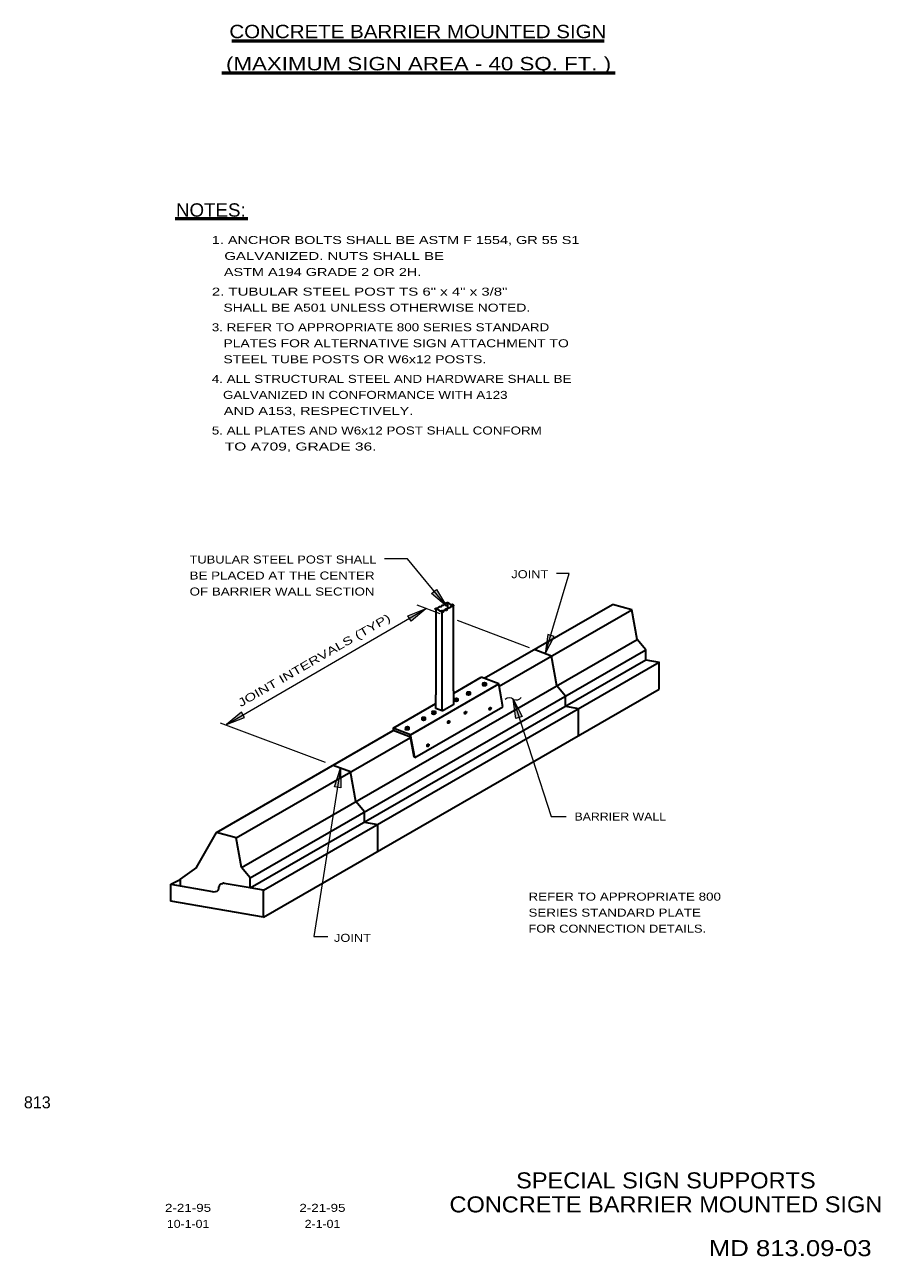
# Model space of a CAD drawing. Extents: x 5940.27 to 5946.69, y 1537.87 to 1547.1.
import ezdxf
from ezdxf.enums import TextEntityAlignment as Align

# ---------------------------------------------------------------- set-up
doc = ezdxf.new("R2010")
doc.units = 0
doc.header["$LTSCALE"] = 0.024
doc.header["$PDMODE"] = 32
doc.header["$PDSIZE"] = 0.012
for name, color, linetype, lineweight in [('1', 7, 'Continuous', 35), ('10', 7, 'Continuous', 13), ('12', 7, 'Continuous', 53), ('13', 7, 'Continuous', 53)]:
    doc.layers.add(name, color=color, linetype=linetype, lineweight=lineweight)

msp = doc.modelspace()

# ---------------------------------------------------------------- hatches: boundary and pattern name
at = {"layer": '10'}
for points in [[(5943.325, 1542.835), (5943.361, 1542.866), (5943.436, 1542.741)], [(5943.173, 1542.628), (5943.147, 1542.669), (5943.284, 1542.722)], [(5944.244, 1542.514), (5944.198, 1542.528), (5944.177, 1542.384)], [(5944.005, 1541.912), (5943.957, 1541.897), (5943.936, 1542.042)], [(5941.923, 1541.905), (5941.9, 1541.946), (5941.786, 1541.853)], [(5942.645, 1541.379), (5942.596, 1541.387), (5942.643, 1541.526)]]:
    msp.add_hatch(color=256, dxfattribs=at).paths.add_polyline_path(points)

# ---------------------------------------------------------------- linework, layer by layer
at = {"layer": '1'}
for p, q in [((5943.359, 1542.075), (5943.359, 1542.719)), ((5943.405, 1542.056), (5943.405, 1542.698)), ((5943.444, 1542.767), (5943.444, 1542.724)), ((5943.489, 1542.655), (5943.489, 1542.744)), ((5943.72, 1542.2), (5944.682, 1542.754)), ((5943.831, 1542.14), (5944.827, 1542.714)), ((5944.827, 1542.714), (5944.682, 1542.754)), ((5944.867, 1542.491), (5944.827, 1542.714)), ((5943.489, 1542.105), (5943.489, 1542.655)), ((5941.9, 1540.781), (5944.867, 1542.491)), ((5941.964, 1540.703), (5944.933, 1542.414)), ((5944.224, 1542.366), (5944.095, 1542.415)), ((5944.933, 1542.414), (5944.867, 1542.491)), ((5944.933, 1542.338), (5944.933, 1542.414)), ((5941.964, 1540.628), (5944.933, 1542.338)), ((5942.064, 1540.611), (5945.031, 1542.32)), ((5944.264, 1542.143), (5944.224, 1542.366)), ((5944.933, 1542.338), (5945.031, 1542.32)), ((5945.031, 1542.119), (5945.031, 1542.32)), ((5943.168, 1541.777), (5943.829, 1542.158)), ((5943.491, 1542.088), (5943.698, 1542.208)), ((5943.829, 1542.158), (5943.698, 1542.208)), ((5943.709, 1542.164), (5943.709, 1542.147)), ((5943.709, 1542.164), (5943.709, 1542.147)), ((5943.709, 1542.164), (5943.709, 1542.147)), ((5943.709, 1542.164), (5943.709, 1542.147)), ((5943.734, 1542.163), (5943.734, 1542.146)), ((5943.734, 1542.163), (5943.734, 1542.146)), ((5943.734, 1542.163), (5943.734, 1542.146)), ((5943.734, 1542.163), (5943.734, 1542.146)), ((5943.86, 1541.986), (5943.829, 1542.158)), ((5944.33, 1542.066), (5944.264, 1542.143)), ((5942.064, 1540.408), (5945.031, 1542.119)), ((5943.357, 1541.973), (5943.357, 1542.075)), ((5943.404, 1541.956), (5943.404, 1542.055)), ((5943.498, 1542.048), (5943.498, 1542.031)), ((5943.498, 1542.048), (5943.498, 1542.031)), ((5943.523, 1542.047), (5943.523, 1542.03)), ((5943.523, 1542.047), (5943.523, 1542.03)), ((5943.59, 1542.096), (5943.59, 1542.079)), ((5943.59, 1542.096), (5943.59, 1542.079)), ((5943.59, 1542.096), (5943.59, 1542.079)), ((5943.59, 1542.096), (5943.59, 1542.079)), ((5943.615, 1542.095), (5943.615, 1542.078)), ((5943.615, 1542.095), (5943.615, 1542.078)), ((5943.615, 1542.095), (5943.615, 1542.078)), ((5943.615, 1542.095), (5943.615, 1542.078)), ((5944.33, 1541.99), (5944.33, 1542.066)), ((5943.037, 1541.826), (5943.357, 1542.01)), ((5943.199, 1541.605), (5943.86, 1541.986)), ((5943.329, 1541.951), (5943.329, 1541.934)), ((5943.354, 1541.95), (5943.354, 1541.933)), ((5943.404, 1541.956), (5943.357, 1541.973)), ((5944.33, 1541.99), (5944.428, 1541.972)), ((5944.428, 1541.771), (5944.428, 1541.972)), ((5943.253, 1541.906), (5943.253, 1541.889)), ((5943.278, 1541.905), (5943.278, 1541.888)), ((5941.713, 1541.043), (5943.038, 1541.807)), ((5943.168, 1541.777), (5943.037, 1541.826)), ((5943.037, 1541.826), (5943.037, 1541.806)), ((5943.168, 1541.758), (5943.038, 1541.807)), ((5943.13, 1541.834), (5943.13, 1541.817)), ((5943.155, 1541.833), (5943.155, 1541.816)), ((5943.168, 1541.777), (5943.168, 1541.758)), ((5943.199, 1541.605), (5943.168, 1541.777)), ((5941.86, 1541.004), (5943.166, 1541.757)), ((5943.195, 1541.608), (5943.168, 1541.758)), ((5943.194, 1541.608), (5943.198, 1541.606)), ((5942.717, 1541.498), (5942.588, 1541.547)), ((5942.757, 1541.275), (5942.717, 1541.498)), ((5942.823, 1541.198), (5942.757, 1541.275)), ((5942.823, 1541.122), (5942.823, 1541.198)), ((5942.823, 1541.122), (5942.921, 1541.104)), ((5941.562, 1540.781), (5941.713, 1541.043)), ((5941.86, 1541.004), (5941.713, 1541.043)), ((5942.921, 1540.903), (5942.921, 1541.104)), ((5941.369, 1540.656), (5941.439, 1540.692)), ((5941.369, 1540.529), (5941.369, 1540.656)), ((5941.369, 1540.656), (5941.682, 1540.601)), ((5941.964, 1540.628), (5941.769, 1540.662)), ((5942.064, 1540.408), (5942.064, 1540.611)), ((5942.064, 1540.408), (5941.369, 1540.529))]:
    msp.add_line(p, q, dxfattribs=at)
for points in [[(5943.358, 1542.719), (5943.361, 1542.722), (5943.362, 1542.722), (5943.365, 1542.724), (5943.367, 1542.724), (5943.368, 1542.724), (5943.368, 1542.725), (5943.371, 1542.725), (5943.372, 1542.727), (5943.374, 1542.727), (5943.375, 1542.728), (5943.376, 1542.731), (5943.378, 1542.734), (5943.381, 1542.735), (5943.382, 1542.735), (5943.384, 1542.737), (5943.385, 1542.737), (5943.386, 1542.737), (5943.389, 1542.738), (5943.392, 1542.738), (5943.396, 1542.738), (5943.399, 1542.739), (5943.401, 1542.741), (5943.402, 1542.742), (5943.404, 1542.744), (5943.404, 1542.745), (5943.405, 1542.747), (5943.406, 1542.747), (5943.408, 1542.749), (5943.411, 1542.749), (5943.412, 1542.749), (5943.415, 1542.749), (5943.416, 1542.751), (5943.418, 1542.752), (5943.421, 1542.754), (5943.425, 1542.757), (5943.428, 1542.759), (5943.431, 1542.761), (5943.432, 1542.764), (5943.434, 1542.764)], [(5943.402, 1542.701), (5943.399, 1542.701), (5943.398, 1542.704), (5943.395, 1542.704), (5943.392, 1542.704), (5943.389, 1542.704), (5943.386, 1542.704), (5943.385, 1542.705), (5943.384, 1542.707), (5943.384, 1542.708), (5943.382, 1542.708), (5943.381, 1542.711), (5943.378, 1542.711), (5943.376, 1542.712), (5943.374, 1542.714), (5943.369, 1542.715), (5943.367, 1542.715), (5943.365, 1542.715), (5943.362, 1542.717), (5943.361, 1542.717), (5943.359, 1542.719)], [(5943.411, 1542.701), (5943.406, 1542.7), (5943.405, 1542.7), (5943.405, 1542.698), (5943.404, 1542.7), (5943.402, 1542.701)], [(5943.436, 1542.715), (5943.435, 1542.714), (5943.434, 1542.712), (5943.432, 1542.711), (5943.429, 1542.711), (5943.426, 1542.709), (5943.425, 1542.709), (5943.422, 1542.709), (5943.421, 1542.709), (5943.419, 1542.708), (5943.418, 1542.708), (5943.416, 1542.707), (5943.415, 1542.705), (5943.414, 1542.704), (5943.412, 1542.704), (5943.411, 1542.701)], [(5943.434, 1542.764), (5943.435, 1542.764), (5943.436, 1542.764), (5943.438, 1542.764), (5943.441, 1542.764), (5943.442, 1542.765), (5943.442, 1542.767), (5943.444, 1542.767), (5943.445, 1542.767), (5943.446, 1542.767), (5943.448, 1542.765), (5943.449, 1542.764), (5943.451, 1542.764), (5943.452, 1542.764), (5943.456, 1542.761), (5943.458, 1542.761), (5943.459, 1542.761), (5943.462, 1542.759), (5943.462, 1542.758), (5943.462, 1542.755), (5943.464, 1542.755), (5943.464, 1542.754), (5943.466, 1542.754), (5943.468, 1542.754), (5943.473, 1542.754), (5943.475, 1542.752), (5943.476, 1542.752), (5943.478, 1542.752), (5943.479, 1542.751), (5943.481, 1542.749)], [(5943.481, 1542.749), (5943.482, 1542.749), (5943.485, 1542.749), (5943.486, 1542.747), (5943.488, 1542.747), (5943.489, 1542.747), (5943.489, 1542.745), (5943.489, 1542.744), (5943.488, 1542.742), (5943.486, 1542.741), (5943.482, 1542.739), (5943.481, 1542.739), (5943.478, 1542.738), (5943.476, 1542.738), (5943.473, 1542.738), (5943.472, 1542.738), (5943.471, 1542.737), (5943.471, 1542.735), (5943.468, 1542.735), (5943.466, 1542.734), (5943.466, 1542.731), (5943.464, 1542.729), (5943.462, 1542.727), (5943.458, 1542.727), (5943.455, 1542.725), (5943.451, 1542.725), (5943.446, 1542.725), (5943.445, 1542.725), (5943.444, 1542.724), (5943.442, 1542.722), (5943.441, 1542.719), (5943.438, 1542.719), (5943.436, 1542.715)], [(5943.404, 1541.956), (5943.491, 1542.006), (5943.491, 1542.105)], [(5942.064, 1540.611), (5941.964, 1540.628), (5941.964, 1540.703), (5941.9, 1540.781), (5941.86, 1541.004)], [(5941.562, 1540.781), (5941.439, 1540.693), (5941.439, 1540.644)], [(5941.68, 1540.601), (5941.682, 1540.601), (5941.693, 1540.599), (5941.704, 1540.602), (5941.716, 1540.604), (5941.722, 1540.609), (5941.727, 1540.615), (5941.729, 1540.626), (5941.729, 1540.636), (5941.734, 1540.645), (5941.74, 1540.654), (5941.747, 1540.658), (5941.754, 1540.661), (5941.759, 1540.662)]]:
    msp.add_lwpolyline(points, dxfattribs=at)
msp.add_arc((5941.76591, 1540.64391), 0.01907, 79.2457, 110.19528, dxfattribs=at)
for centre, major_axis in [((5943.72127, 1542.1497), (0.01323, 0)), ((5943.72127, 1542.1497), (0.01323, 0)), ((5943.72127, 1542.1497), (0.01323, 0)), ((5943.72127, 1542.1497), (0.01323, 0)), ((5943.72227, 1542.1597), (0.01323, 0)), ((5943.72227, 1542.1597), (0.01323, 0)), ((5943.72227, 1542.1597), (0.01323, 0)), ((5943.72227, 1542.1597), (0.01323, 0)), ((5943.51027, 1542.0337), (0.01323, 0)), ((5943.51027, 1542.0337), (0.01323, 0)), ((5943.51127, 1542.0437), (0.01323, 0)), ((5943.51127, 1542.0437), (0.01323, 0)), ((5943.60227, 1542.0817), (0.01323, 0)), ((5943.60227, 1542.0817), (0.01323, 0)), ((5943.60227, 1542.0817), (0.01323, 0)), ((5943.60227, 1542.0817), (0.01323, 0)), ((5943.60327, 1542.0917), (0.01323, 0)), ((5943.60327, 1542.0917), (0.01323, 0)), ((5943.60327, 1542.0917), (0.01323, 0)), ((5943.60327, 1542.0917), (0.01323, 0)), ((5943.34127, 1541.9367), (0.01323, 0)), ((5943.34227, 1541.9467), (0.01323, 0)), ((5943.57927, 1541.9427), (0.00511, 0.00884)), ((5943.76427, 1541.9727), (0.00511, 0.00884)), ((5943.26527, 1541.8917), (0.01323, 0)), ((5943.26627, 1541.9017), (0.01323, 0)), ((5943.45327, 1541.8717), (0.00511, 0.00884)), ((5943.14227, 1541.8197), (0.01323, 0)), ((5943.14327, 1541.8297), (0.01323, 0)), ((5943.29827, 1541.6977), (0.00511, 0.00884))]:
    msp.add_ellipse(centre, major_axis=major_axis, ratio=0.57735, dxfattribs=at)
for p in [(5943.359, 1542.719), (5943.402, 1542.701), (5943.411, 1542.701), (5943.436, 1542.715), (5943.481, 1542.749)]:
    msp.add_point(p, dxfattribs=at)
at = {"layer": '10'}
for p, q in [((5941.786, 1541.852), (5943.285, 1542.724)), ((5943.389, 1542.684), (5943.218, 1542.748)), ((5944.059, 1542.429), (5943.519, 1542.634)), ((5942.53, 1541.569), (5941.743, 1541.863))]:
    msp.add_line(p, q, dxfattribs=at)
for points in [[(5943.436, 1542.741), (5943.144, 1543.096), (5942.973, 1543.096)], [(5944.177, 1542.384), (5944.357, 1542.985), (5944.261, 1542.985)], [(5943.936, 1542.042), (5944.223, 1541.164), (5944.334, 1541.163)], [(5942.643, 1541.526), (5942.443, 1540.265), (5942.548, 1540.265)]]:
    msp.add_lwpolyline(points, dxfattribs=at)
for points in [[(5943.325, 1542.835), (5943.361, 1542.866), (5943.436, 1542.741)], [(5943.173, 1542.628), (5943.147, 1542.669), (5943.284, 1542.722)], [(5944.244, 1542.514), (5944.198, 1542.528), (5944.177, 1542.384)], [(5944.005, 1541.912), (5943.957, 1541.897), (5943.936, 1542.042)], [(5941.923, 1541.905), (5941.9, 1541.946), (5941.786, 1541.853)], [(5942.645, 1541.379), (5942.596, 1541.387), (5942.643, 1541.526)]]:
    msp.add_lwpolyline(points, close=True, dxfattribs=at)
for centre, radius, start, end in [((5943.90928, 1542.00444), 0.04844, 50.11598, 129.88402), ((5943.96061, 1542.08336), 0.04641, 244.09904, 322.98165)]:
    msp.add_arc(centre, radius, start, end, dxfattribs=at)
at = {"layer": '12'}
for p, q in [((5941.826, 1546.978), (5944.62, 1546.978)), ((5941.752, 1546.737), (5944.703, 1546.737))]:
    msp.add_line(p, q, dxfattribs=at)
at = {"layer": '13'}
msp.add_line((5941.402, 1545.647), (5941.947, 1545.647), dxfattribs=at)

# ---------------------------------------------------------------- texts
at = {"layer": '12'}
for s, width, p in [('CONCRETE BARRIER MOUNTED SIGN', 1.15, (5943.2225, 1546.998)), ('(MAXIMUM SIGN AREA - 40 SQ. FT. )', 1.25, (5943.2275, 1546.757))]:
    msp.add_text(s, height=0.1, dxfattribs=dict(at, width=width)).set_placement(p, align=Align.CENTER)
for s, width, p in [('TUBULAR STEEL POST SHALL', 1.2, (5941.51, 1543.06)), ('BE PLACED AT THE CENTER', 1.25, (5941.51, 1542.94)), ('JOINT', 1.2, (5943.923, 1542.95)), ('OF BARRIER WALL SECTION', 1.25, (5941.51, 1542.82)), ('BARRIER WALL', 1.15, (5944.397, 1541.133)), ('REFER TO APPROPRIATE 800', 1.25, (5944.052, 1540.533)), ('SERIES STANDARD PLATE ', 1.25, (5944.052, 1540.413)), ('JOINT', 1.2, (5942.593, 1540.224)), ('FOR CONNECTION DETAILS.', 1.2, (5944.052, 1540.293))]:
    msp.add_text(s, height=0.06, dxfattribs=dict(at, width=width)).set_placement(p)
at = {"layer": '12', "width": 1.4}
msp.add_text(' JOINT INTERVALS (TYP)', height=0.06, rotation=30, dxfattribs=at).set_placement((5941.867, 1541.967))
at = {"layer": '13'}
for s, height, width, p in [('NOTES:', 0.1, 1.05, (5941.6695, 1545.66)), ('SPECIAL SIGN SUPPORTS', 0.12, 1.1, (5945.0825, 1538.376)), ('2-21-95', 0.06, 1.25, (5941.4985, 1538.2)), ('2-21-95', 0.06, 1.25, (5942.5065, 1538.2)), ('CONCRETE BARRIER MOUNTED SIGN', 0.12, 1.1, (5945.0825, 1538.196)), ('10-1-01', 0.06, 1.15, (5941.499, 1538.08)), ('2-1-01', 0.06, 1.15, (5942.507, 1538.08)), ('MD 813.09-03', 0.12, 1.2, (5946.015, 1537.868))]:
    msp.add_text(s, height=height, dxfattribs=dict(at, width=width)).set_placement(p, align=Align.CENTER)
for s, width, p in [('1. ANCHOR BOLTS SHALL BE ASTM F 1554, GR 55 S1', 1.35, (5941.677, 1545.455)), ('   GALVANIZED. NUTS SHALL BE ', 1.4, (5941.677, 1545.335)), ('   ASTM A194 GRADE 2 OR 2H.', 1.35, (5941.677, 1545.215)), ('2. TUBULAR STEEL POST TS 6" x 4" x 3/8"', 1.4, (5941.677, 1545.068)), ('   SHALL BE A501 UNLESS OTHERWISE NOTED.', 1.3, (5941.677, 1544.948)), ('3. REFER TO APPROPRIATE 800 SERIES STANDARD', 1.25, (5941.677, 1544.801)), ('   PLATES FOR ALTERNATIVE SIGN ATTACHMENT TO', 1.3, (5941.677, 1544.681)), ('   STEEL TUBE POSTS OR W6x12 POSTS.', 1.3, (5941.677, 1544.561)), ('4. ALL STRUCTURAL STEEL AND HARDWARE SHALL BE', 1.25, (5941.677, 1544.414)), ('   GALVANIZED IN CONFORMANCE WITH A123', 1.25, (5941.677, 1544.294)), ('   AND A153, RESPECTIVELY.', 1.35, (5941.677, 1544.174)), ('5. ALL PLATES AND W6x12 POST SHALL CONFORM', 1.25, (5941.677, 1544.027)), ('   TO A709, GRADE 36.', 1.45, (5941.677, 1543.907))]:
    msp.add_text(s, height=0.06, dxfattribs=dict(at, width=width)).set_placement(p)
msp.add_text('813', height=0.09, dxfattribs=at).set_placement((5940.368, 1538.976), align=Align.CENTER)

doc.saveas('drawing.dxf')
